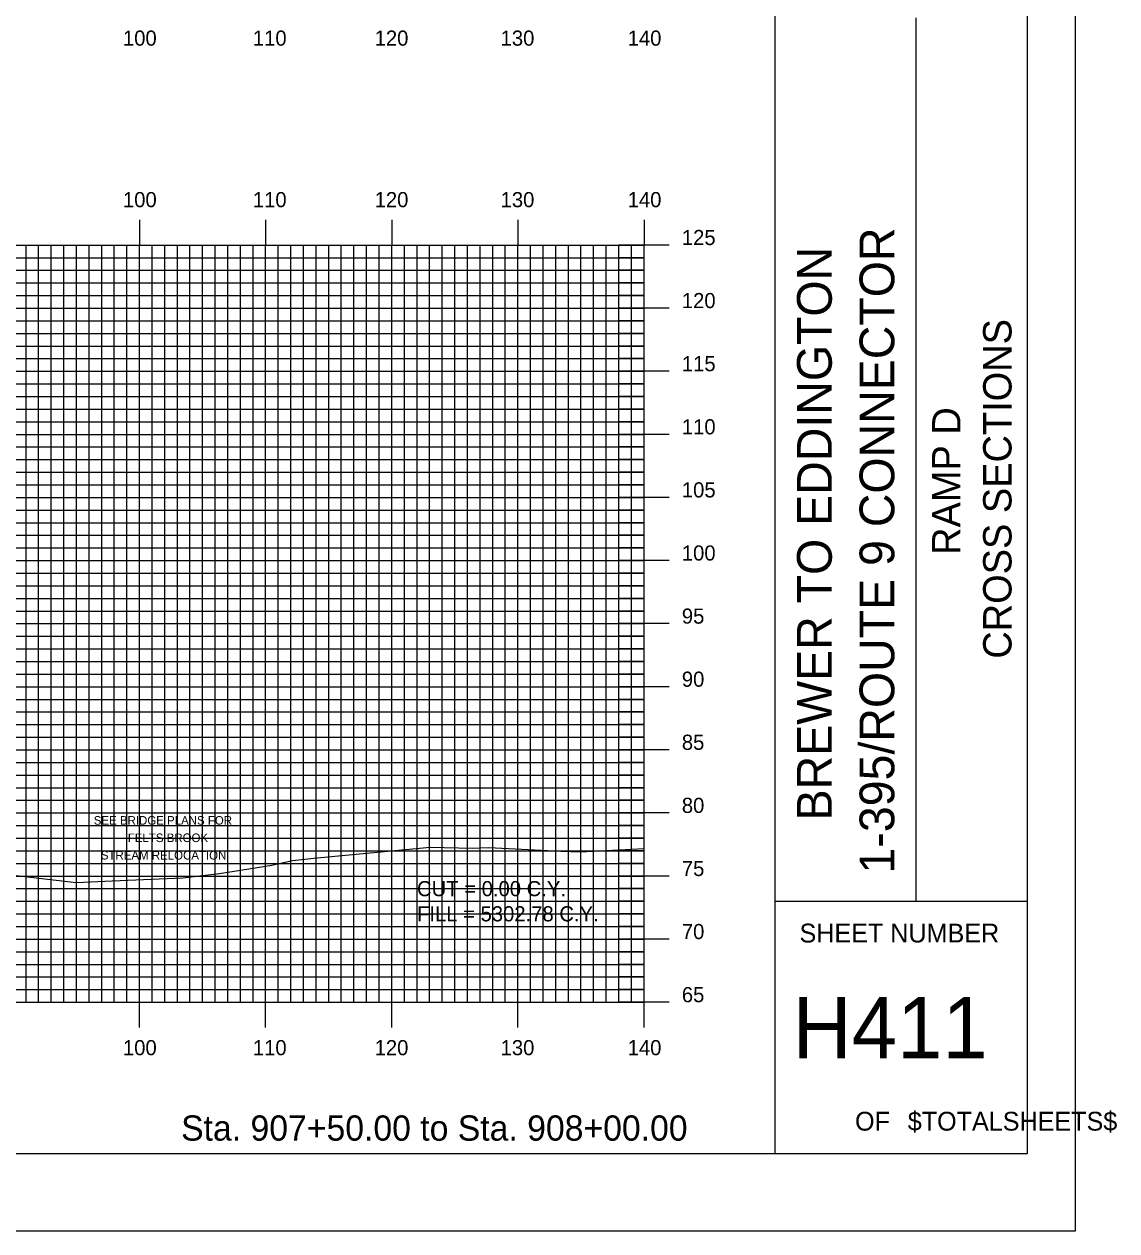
# Model space of a CAD drawing. Extents: x 858291 to 858634, y 364765 to 364985.
# Drawn here: x 858547.2 to 858633.8, y 364765.2 to 364860.8 of the extents above; entities that cross this region are included whole.
import ezdxf

# ---------------------------------------------------------------- set-up
doc = ezdxf.new("R2010")
doc.units = 0
for name, color, linetype in [('ANNOTATION', 7, 'Continuous'), ('BORDER', 7, 'Continuous'), ('D_Text_Standard', 7, 'Continuous'), ('H_V ANNOTATION', 7, 'Continuous'), ('MAJOR', 7, 'Continuous'), ('MINOR', 7, 'Continuous'), ('PLOT BOUNDARY', 7, 'Continuous'), ('S_Roadway_Centerline', 7, 'Continuous')]:
    doc.layers.add(name, color=color, linetype=linetype)

msp = doc.modelspace()

# ---------------------------------------------------------------- linework, layer by layer
at = {"layer": 'BORDER'}
for p, q in [((858606.734, 364771.302), (858606.734, 364981.302)), ((858617.916, 364791.308), (858617.916, 364861.308)), ((858606.734, 364791.308), (858626.734, 364791.308))]:
    msp.add_line(p, q, dxfattribs=at)
msp.add_lwpolyline([(858306.734, 364771.302), (858626.734, 364771.302), (858626.734, 364981.302), (858306.734, 364981.302)], close=True, dxfattribs=at)
at = {"layer": 'MAJOR'}
for p, q in [((858556.334, 364845.306), (858556.334, 364843.302)), ((858566.334, 364845.306), (858566.334, 364843.302)), ((858576.334, 364845.306), (858576.334, 364843.302)), ((858586.334, 364845.306), (858586.334, 364843.302)), ((858596.334, 364845.306), (858596.334, 364843.302)), ((858316.334, 364843.302), (858596.334, 364843.302)), ((858316.334, 364843.302), (858596.334, 364843.302)), ((858556.334, 364783.302), (858556.334, 364843.302)), ((858566.334, 364783.302), (858566.334, 364843.302)), ((858576.334, 364783.302), (858576.334, 364843.302)), ((858586.334, 364783.302), (858586.334, 364843.302)), ((858598.338, 364843.302), (858594.33, 364843.302)), ((858596.334, 364783.302), (858596.334, 364843.302)), ((858596.334, 364783.302), (858596.334, 364843.302)), ((858316.334, 364838.302), (858596.334, 364838.302)), ((858598.338, 364838.302), (858594.33, 364838.302)), ((858316.334, 364833.302), (858596.334, 364833.302)), ((858598.338, 364833.302), (858594.33, 364833.302)), ((858316.334, 364828.302), (858596.334, 364828.302)), ((858598.338, 364828.302), (858594.33, 364828.302)), ((858316.334, 364823.302), (858596.334, 364823.302)), ((858598.338, 364823.302), (858594.33, 364823.302)), ((858316.334, 364818.302), (858596.334, 364818.302)), ((858598.338, 364818.302), (858594.33, 364818.302)), ((858316.334, 364813.302), (858596.334, 364813.302)), ((858598.338, 364813.302), (858594.33, 364813.302)), ((858316.334, 364808.302), (858596.334, 364808.302)), ((858598.338, 364808.302), (858594.33, 364808.302)), ((858316.334, 364803.302), (858596.334, 364803.302)), ((858598.338, 364803.302), (858594.33, 364803.302)), ((858316.334, 364798.302), (858596.334, 364798.302)), ((858598.338, 364798.302), (858594.33, 364798.302)), ((858316.334, 364793.302), (858596.334, 364793.302)), ((858598.338, 364793.302), (858594.33, 364793.302)), ((858316.334, 364788.302), (858596.334, 364788.302)), ((858598.338, 364788.302), (858594.33, 364788.302)), ((858316.334, 364783.302), (858596.334, 364783.302)), ((858316.334, 364783.302), (858596.334, 364783.302)), ((858556.334, 364781.298), (858556.334, 364783.302)), ((858566.334, 364781.298), (858566.334, 364783.302)), ((858576.334, 364781.298), (858576.334, 364783.302)), ((858586.334, 364781.298), (858586.334, 364783.302)), ((858598.338, 364783.302), (858594.33, 364783.302)), ((858596.334, 364781.298), (858596.334, 364783.302))]:
    msp.add_line(p, q, dxfattribs=at)
at = {"layer": 'MINOR'}
for p, q in [((858547.334, 364783.302), (858547.334, 364843.302)), ((858548.334, 364783.302), (858548.334, 364843.302)), ((858549.334, 364783.302), (858549.334, 364843.302)), ((858550.334, 364783.302), (858550.334, 364843.302)), ((858551.334, 364783.302), (858551.334, 364843.302)), ((858552.334, 364783.302), (858552.334, 364843.302)), ((858553.334, 364783.302), (858553.334, 364843.302)), ((858554.334, 364783.302), (858554.334, 364843.302)), ((858555.334, 364783.302), (858555.334, 364843.302)), ((858557.334, 364783.302), (858557.334, 364843.302)), ((858558.334, 364783.302), (858558.334, 364843.302)), ((858559.334, 364783.302), (858559.334, 364843.302)), ((858560.334, 364783.302), (858560.334, 364843.302)), ((858561.334, 364783.302), (858561.334, 364843.302)), ((858562.334, 364783.302), (858562.334, 364843.302)), ((858563.334, 364783.302), (858563.334, 364843.302)), ((858564.334, 364783.302), (858564.334, 364843.302)), ((858565.334, 364783.302), (858565.334, 364843.302)), ((858567.334, 364783.302), (858567.334, 364843.302)), ((858568.334, 364783.302), (858568.334, 364843.302)), ((858569.334, 364783.302), (858569.334, 364843.302)), ((858570.334, 364783.302), (858570.334, 364843.302)), ((858571.334, 364783.302), (858571.334, 364843.302)), ((858572.334, 364783.302), (858572.334, 364843.302)), ((858573.334, 364783.302), (858573.334, 364843.302)), ((858574.334, 364783.302), (858574.334, 364843.302)), ((858575.334, 364783.302), (858575.334, 364843.302)), ((858577.334, 364783.302), (858577.334, 364843.302)), ((858578.334, 364783.302), (858578.334, 364843.302)), ((858579.334, 364783.302), (858579.334, 364843.302)), ((858580.334, 364783.302), (858580.334, 364843.302)), ((858581.334, 364783.302), (858581.334, 364843.302)), ((858582.334, 364783.302), (858582.334, 364843.302)), ((858583.334, 364783.302), (858583.334, 364843.302)), ((858584.334, 364783.302), (858584.334, 364843.302)), ((858585.334, 364783.302), (858585.334, 364843.302)), ((858587.334, 364783.302), (858587.334, 364843.302)), ((858588.334, 364783.302), (858588.334, 364843.302)), ((858589.334, 364783.302), (858589.334, 364843.302)), ((858590.334, 364783.302), (858590.334, 364843.302)), ((858591.334, 364783.302), (858591.334, 364843.302)), ((858592.334, 364783.302), (858592.334, 364843.302)), ((858593.334, 364783.302), (858593.334, 364843.302)), ((858594.334, 364783.302), (858594.334, 364843.302)), ((858595.334, 364783.302), (858595.334, 364843.302)), ((858316.334, 364842.302), (858596.334, 364842.302)), ((858596.334, 364842.302), (858594.33, 364842.302)), ((858316.334, 364841.302), (858596.334, 364841.302)), ((858596.334, 364841.302), (858594.33, 364841.302)), ((858316.334, 364840.302), (858596.334, 364840.302)), ((858596.334, 364840.302), (858594.33, 364840.302)), ((858316.334, 364839.302), (858596.334, 364839.302)), ((858596.334, 364839.302), (858594.33, 364839.302)), ((858316.334, 364837.302), (858596.334, 364837.302)), ((858596.334, 364837.302), (858594.33, 364837.302)), ((858316.334, 364836.302), (858596.334, 364836.302)), ((858596.334, 364836.302), (858594.33, 364836.302)), ((858316.334, 364835.302), (858596.334, 364835.302)), ((858596.334, 364835.302), (858594.33, 364835.302)), ((858316.334, 364834.302), (858596.334, 364834.302)), ((858596.334, 364834.302), (858594.33, 364834.302)), ((858316.334, 364832.302), (858596.334, 364832.302)), ((858596.334, 364832.302), (858594.33, 364832.302)), ((858316.334, 364831.302), (858596.334, 364831.302)), ((858596.334, 364831.302), (858594.33, 364831.302)), ((858316.334, 364830.302), (858596.334, 364830.302)), ((858596.334, 364830.302), (858594.33, 364830.302)), ((858316.334, 364829.302), (858596.334, 364829.302)), ((858596.334, 364829.302), (858594.33, 364829.302)), ((858316.334, 364827.302), (858596.334, 364827.302)), ((858596.334, 364827.302), (858594.33, 364827.302)), ((858316.334, 364826.302), (858596.334, 364826.302)), ((858596.334, 364826.302), (858594.33, 364826.302)), ((858316.334, 364825.302), (858596.334, 364825.302)), ((858596.334, 364825.302), (858594.33, 364825.302)), ((858316.334, 364824.302), (858596.334, 364824.302)), ((858596.334, 364824.302), (858594.33, 364824.302)), ((858316.334, 364822.302), (858596.334, 364822.302)), ((858596.334, 364822.302), (858594.33, 364822.302)), ((858316.334, 364821.302), (858596.334, 364821.302)), ((858596.334, 364821.302), (858594.33, 364821.302)), ((858316.334, 364820.302), (858596.334, 364820.302)), ((858596.334, 364820.302), (858594.33, 364820.302)), ((858316.334, 364819.302), (858596.334, 364819.302)), ((858596.334, 364819.302), (858594.33, 364819.302)), ((858316.334, 364817.302), (858596.334, 364817.302)), ((858596.334, 364817.302), (858594.33, 364817.302)), ((858316.334, 364816.302), (858596.334, 364816.302)), ((858596.334, 364816.302), (858594.33, 364816.302)), ((858316.334, 364815.302), (858596.334, 364815.302)), ((858596.334, 364815.302), (858594.33, 364815.302)), ((858316.334, 364814.302), (858596.334, 364814.302)), ((858596.334, 364814.302), (858594.33, 364814.302)), ((858316.334, 364812.302), (858596.334, 364812.302)), ((858596.334, 364812.302), (858594.33, 364812.302)), ((858316.334, 364811.302), (858596.334, 364811.302)), ((858596.334, 364811.302), (858594.33, 364811.302)), ((858316.334, 364810.302), (858596.334, 364810.302)), ((858596.334, 364810.302), (858594.33, 364810.302)), ((858316.334, 364809.302), (858596.334, 364809.302)), ((858596.334, 364809.302), (858594.33, 364809.302)), ((858316.334, 364807.302), (858596.334, 364807.302)), ((858596.334, 364807.302), (858594.33, 364807.302)), ((858316.334, 364806.302), (858596.334, 364806.302)), ((858596.334, 364806.302), (858594.33, 364806.302)), ((858316.334, 364805.302), (858596.334, 364805.302)), ((858596.334, 364805.302), (858594.33, 364805.302)), ((858316.334, 364804.302), (858596.334, 364804.302)), ((858596.334, 364804.302), (858594.33, 364804.302)), ((858316.334, 364802.302), (858596.334, 364802.302)), ((858596.334, 364802.302), (858594.33, 364802.302)), ((858316.334, 364801.302), (858596.334, 364801.302)), ((858596.334, 364801.302), (858594.33, 364801.302)), ((858316.334, 364800.302), (858596.334, 364800.302)), ((858596.334, 364800.302), (858594.33, 364800.302)), ((858316.334, 364799.302), (858596.334, 364799.302)), ((858596.334, 364799.302), (858594.33, 364799.302)), ((858316.334, 364797.302), (858596.334, 364797.302)), ((858596.334, 364797.302), (858594.33, 364797.302)), ((858316.334, 364796.302), (858596.334, 364796.302)), ((858596.334, 364796.302), (858594.33, 364796.302)), ((858316.334, 364795.302), (858596.334, 364795.302)), ((858596.334, 364795.302), (858594.33, 364795.302)), ((858316.334, 364794.302), (858596.334, 364794.302)), ((858596.334, 364794.302), (858594.33, 364794.302)), ((858316.334, 364792.302), (858596.334, 364792.302)), ((858596.334, 364792.302), (858594.33, 364792.302)), ((858316.334, 364791.302), (858596.334, 364791.302)), ((858596.334, 364791.302), (858594.33, 364791.302)), ((858316.334, 364790.302), (858596.334, 364790.302)), ((858596.334, 364790.302), (858594.33, 364790.302)), ((858316.334, 364789.302), (858596.334, 364789.302)), ((858596.334, 364789.302), (858594.33, 364789.302)), ((858316.334, 364787.302), (858596.334, 364787.302)), ((858596.334, 364787.302), (858594.33, 364787.302)), ((858316.334, 364786.302), (858596.334, 364786.302)), ((858596.334, 364786.302), (858594.33, 364786.302)), ((858316.334, 364785.302), (858596.334, 364785.302)), ((858596.334, 364785.302), (858594.33, 364785.302)), ((858316.334, 364784.302), (858596.334, 364784.302)), ((858596.334, 364784.302), (858594.33, 364784.302))]:
    msp.add_line(p, q, dxfattribs=at)
at = {"layer": 'PLOT BOUNDARY'}
msp.add_lwpolyline([(858290.547, 364765.184), (858630.547, 364765.184), (858630.547, 364985.184), (858290.547, 364985.184)], close=True, dxfattribs=at)
at = {"layer": 'S_Roadway_Centerline'}
msp.add_lwpolyline([(858546.111, 364793.393), (858551.3, 364792.791), (858554.163, 364792.933), (858559.778, 364793.17), (858562.666, 364793.499), (858566.83, 364794.156), (858568.475, 364794.545), (858570.162, 364794.722), (858579.379, 364795.599), (858582.745, 364795.499), (858584.039, 364795.556), (858589.745, 364795.273), (858591.298, 364795.232), (858596.334, 364795.497)], dxfattribs=at)

# ---------------------------------------------------------------- texts
at = {"layer": 'ANNOTATION'}
for s, p in [('SEE BRIDGE PLANS FOR', (858552.704, 364797.372)), ('FELTS BROOK ', (858555.405, 364795.992)), ('STREAM RELOCATION', (858553.264, 364794.612))]:
    msp.add_text(s, height=0.68, dxfattribs=at).set_placement(p)
at = {"layer": 'BORDER'}
for s, height, p in [('1-395/ROUTE 9 CONNECTOR', 2.75575, (858616.183, 364793.502)), ('BREWER TO EDDINGTON', 2.75575, (858611.223, 364797.711)), ('CROSS SECTIONS', 2.25, (858625.475, 364810.524)), ('RAMP D', 2.25, (858621.425, 364818.752))]:
    msp.add_text(s, height=height, rotation=90, dxfattribs=at).set_placement(p)
for s, height, p in [('SHEET NUMBER', 1.49054, (858608.665, 364788.035)), ('H411', 4.8388, (858608.127, 364778.867)), ('OF', 1.4905, (858613.068, 364773.128)), ('$TOTALSHEETS$', 1.49054, (858617.247, 364773.128))]:
    msp.add_text(s, height=height, dxfattribs=at).set_placement(p)
at = {"layer": 'D_Text_Standard'}
for s, p in [('CUT = 0.00 C.Y.', (858578.334, 364791.702)), ('FILL = 5302.78 C.Y.', (858578.334, 364789.71))]:
    msp.add_text(s, height=1.2, dxfattribs=at).set_placement(p)
at = {"layer": 'H_V ANNOTATION'}
for s, height, p in [('100', 1.2, (858555.017, 364859.102)), ('110', 1.2, (858565.317, 364859.102)), ('120', 1.2, (858574.974, 364859.102)), ('130', 1.2, (858584.964, 364859.102)), ('140', 1.2, (858595.039, 364859.102)), ('100', 1.2, (858555.017, 364846.302)), ('110', 1.2, (858565.317, 364846.302)), ('120', 1.2, (858574.974, 364846.302)), ('130', 1.2, (858584.964, 364846.302)), ('140', 1.2, (858595.039, 364846.302)), ('125', 1.2, (858599.334, 364843.302)), ('120', 1.2, (858599.334, 364838.302)), ('115', 1.2, (858599.334, 364833.302)), ('110', 1.2, (858599.334, 364828.302)), ('105', 1.2, (858599.334, 364823.302)), ('100', 1.2, (858599.334, 364818.302)), ('95', 1.2, (858599.334, 364813.302)), ('90', 1.2, (858599.334, 364808.302)), ('85', 1.2, (858599.334, 364803.302)), ('80', 1.2, (858599.334, 364798.302)), ('75', 1.2, (858599.334, 364793.302)), ('70', 1.2, (858599.334, 364788.302)), ('65', 1.2, (858599.334, 364783.302)), ('100', 1.2, (858555.017, 364779.102)), ('110', 1.2, (858565.317, 364779.102)), ('120', 1.2, (858574.974, 364779.102)), ('130', 1.2, (858584.964, 364779.102)), ('140', 1.2, (858595.039, 364779.102)), ('Sta. 907+50.00 to Sta. 908+00.00', 2.0004, (858559.631, 364772.332))]:
    msp.add_text(s, height=height, dxfattribs=at).set_placement(p)

doc.saveas('drawing.dxf')
